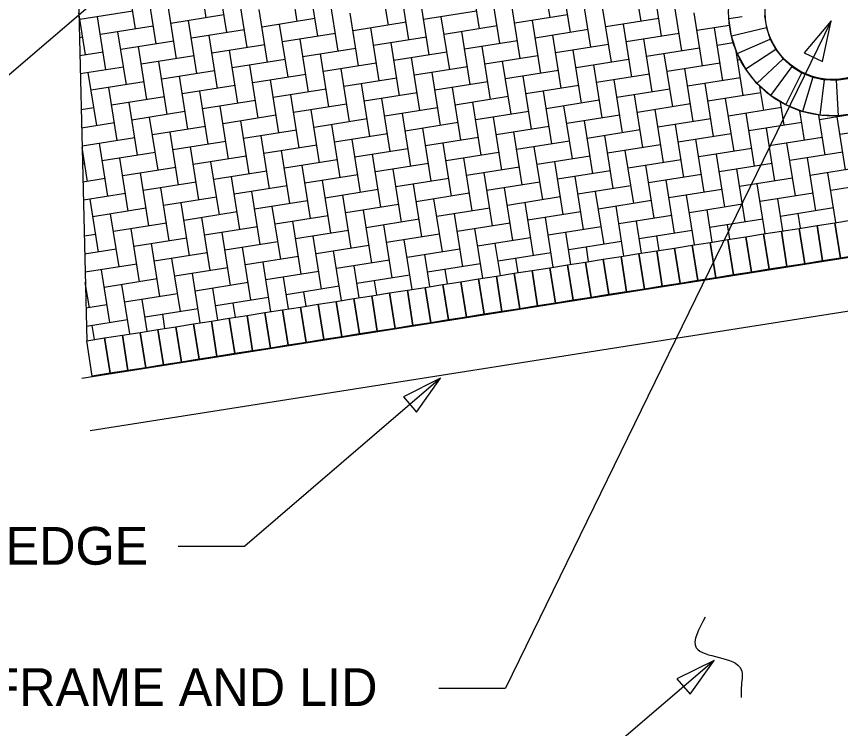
# Model space of a CAD drawing. Extents: x -848 to 1, y -1131 to -115.
# Drawn here: x -814.58 to -783.96, y -835.49 to -809.04 of the extents above; entities that cross this region are included whole.
import ezdxf

# ---------------------------------------------------------------- set-up
doc = ezdxf.new("R2010")
doc.units = 0
for name, color, linetype in [('PM_P_Crosswalk', 7, 'Continuous'), ('PV_P_Joint', 7, 'Continuous'), ('TX_X_5', 7, 'Continuous')]:
    doc.layers.add(name, color=color, linetype=linetype)

msp = doc.modelspace()

# ---------------------------------------------------------------- linework, layer by layer
at = {"layer": 'PM_P_Crosswalk'}
for p, q in [((-766.754, -815.325), (-812.147, -822.484)), ((-766.446, -817.276), (-811.839, -824.435))]:
    msp.add_line(p, q, dxfattribs=at)
at = {"layer": 'PV_P_Joint'}
for p, q in [((-812.301, -807.329), (-811.969, -821.084)), ((-812.301, -807.329), (-811.969, -821.084)), ((-807.528, -809.087), (-807.839, -807.12)), ((-804.145, -809.224), (-804.456, -807.256)), ((-800.762, -809.36), (-801.073, -807.393)), ((-794.755, -809.081), (-795.067, -807.114)), ((-791.372, -809.217), (-791.684, -807.25)), ((-810.151, -809.503), (-810.463, -807.535)), ((-806.768, -809.639), (-807.08, -807.672)), ((-797.379, -809.496), (-797.69, -807.529)), ((-793.996, -809.633), (-794.307, -807.665)), ((-803.385, -809.776), (-803.697, -807.808)), ((-800.002, -809.912), (-800.314, -807.945)), ((-790.613, -809.769), (-790.924, -807.802)), ((-809.391, -810.055), (-809.703, -808.087)), ((-806.008, -810.191), (-806.32, -808.224)), ((-796.619, -810.048), (-796.931, -808.081)), ((-793.236, -810.185), (-793.548, -808.217)), ((-802.625, -810.327), (-802.937, -808.36)), ((-799.242, -810.464), (-799.554, -808.496)), ((-789.853, -810.321), (-790.165, -808.354)), ((-812.015, -810.47), (-812.263, -808.901)), ((-810.255, -808.847), (-812.222, -809.158)), ((-808.632, -810.607), (-808.943, -808.639)), ((-805.249, -810.743), (-805.56, -808.775)), ((-801.866, -810.879), (-802.177, -808.912)), ((-797.483, -808.841), (-799.45, -809.152)), ((-795.859, -810.6), (-796.171, -808.633)), ((-792.476, -810.737), (-792.788, -808.769)), ((-789.093, -810.873), (-789.405, -808.906)), ((-811.255, -811.022), (-811.567, -809.055)), ((-806.872, -808.983), (-808.839, -809.295)), ((-807.872, -811.158), (-808.184, -809.191)), ((-803.489, -809.12), (-805.456, -809.431)), ((-798.483, -811.016), (-798.794, -809.048)), ((-794.1, -808.977), (-796.067, -809.289)), ((-795.1, -811.152), (-795.411, -809.185)), ((-790.717, -809.114), (-792.684, -809.425)), ((-809.495, -809.399), (-811.463, -809.71)), ((-806.112, -809.535), (-808.08, -809.847)), ((-804.489, -811.295), (-804.801, -809.327)), ((-800.106, -809.256), (-802.073, -809.568)), ((-801.106, -811.431), (-801.418, -809.464)), ((-796.723, -809.393), (-798.69, -809.704)), ((-793.34, -809.529), (-795.307, -809.841)), ((-791.717, -811.289), (-792.028, -809.321)), ((-788.086, -809.369), (-789.301, -809.562)), ((-788.334, -811.425), (-788.645, -809.458)), ((-812.118, -809.814), (-812.241, -809.834)), ((-810.495, -811.574), (-810.807, -809.606)), ((-807.112, -811.71), (-807.424, -809.743)), ((-802.729, -809.672), (-804.697, -809.983)), ((-799.346, -809.808), (-801.314, -810.12)), ((-797.723, -811.568), (-798.035, -809.6)), ((-794.34, -811.704), (-794.652, -809.737)), ((-789.957, -809.666), (-791.924, -809.977)), ((-808.735, -809.951), (-810.703, -810.262)), ((-805.352, -810.087), (-807.32, -810.399)), ((-803.729, -811.847), (-804.041, -809.879)), ((-800.346, -811.983), (-800.658, -810.016)), ((-795.963, -809.945), (-797.931, -810.256)), ((-796.963, -812.12), (-797.275, -810.152)), ((-792.58, -810.081), (-794.548, -810.393)), ((-790.957, -811.841), (-791.269, -809.873)), ((-787.946, -810.019), (-788.541, -810.114)), ((-786.576, -809.881), (-786.367, -810.266)), ((-811.359, -810.366), (-812.224, -810.503)), ((-809.736, -812.126), (-810.047, -810.158)), ((-806.353, -812.262), (-806.664, -810.295)), ((-801.97, -810.224), (-803.937, -810.535)), ((-802.97, -812.399), (-803.281, -810.431)), ((-798.587, -810.36), (-800.554, -810.672)), ((-793.58, -812.256), (-793.892, -810.289)), ((-789.197, -810.218), (-791.165, -810.529)), ((-790.197, -812.393), (-790.509, -810.425)), ((-787.574, -811.977), (-787.835, -810.331)), ((-787.802, -810.411), (-787.484, -811.001)), ((-786.367, -810.266), (-787.484, -811.001)), ((-807.976, -810.503), (-809.943, -810.814)), ((-808.976, -812.678), (-809.287, -810.71)), ((-804.593, -810.639), (-806.56, -810.951)), ((-799.587, -812.535), (-799.898, -810.568)), ((-795.204, -810.497), (-797.171, -810.808)), ((-796.204, -812.672), (-796.515, -810.704)), ((-791.821, -810.633), (-793.788, -810.945)), ((-787.688, -810.651), (-787.782, -810.666)), ((-810.599, -810.918), (-812.208, -811.173)), ((-807.216, -811.055), (-809.184, -811.366)), ((-805.593, -812.814), (-805.904, -810.847)), ((-801.21, -810.776), (-803.177, -811.087)), ((-802.21, -812.951), (-802.521, -810.983)), ((-797.827, -810.912), (-799.794, -811.224)), ((-794.444, -811.048), (-796.411, -811.36)), ((-792.821, -812.808), (-793.132, -810.841)), ((-788.438, -810.769), (-790.405, -811.081)), ((-789.438, -812.945), (-789.749, -810.977)), ((-811.599, -813.093), (-811.911, -811.126)), ((-808.216, -813.23), (-808.528, -811.262)), ((-803.833, -811.191), (-805.801, -811.503)), ((-800.45, -811.328), (-802.418, -811.639)), ((-798.827, -813.087), (-799.138, -811.12)), ((-795.444, -813.224), (-795.755, -811.256)), ((-791.061, -811.185), (-793.028, -811.497)), ((-787.678, -811.321), (-789.645, -811.633)), ((-809.839, -811.47), (-811.807, -811.782)), ((-810.839, -813.645), (-811.151, -811.678)), ((-806.456, -811.607), (-808.424, -811.918)), ((-804.833, -813.366), (-805.145, -811.399)), ((-801.45, -813.503), (-801.762, -811.535)), ((-797.067, -811.464), (-799.035, -811.776)), ((-798.067, -813.639), (-798.379, -811.672)), ((-793.684, -811.6), (-795.652, -811.912)), ((-792.061, -813.36), (-792.372, -811.393)), ((-788.678, -813.497), (-788.989, -811.529)), ((-786.814, -812.529), (-786.955, -811.642)), ((-807.456, -813.782), (-807.768, -811.814)), ((-803.073, -811.743), (-805.041, -812.055)), ((-804.073, -813.918), (-804.385, -811.951)), ((-799.69, -811.879), (-801.658, -812.191)), ((-794.684, -813.776), (-794.996, -811.808)), ((-790.301, -811.737), (-792.269, -812.049)), ((-791.301, -813.912), (-791.613, -811.945)), ((-786.918, -811.873), (-788.886, -812.185)), ((-809.08, -812.022), (-811.047, -812.334)), ((-810.08, -814.197), (-810.391, -812.23)), ((-805.697, -812.158), (-807.664, -812.47)), ((-802.314, -812.295), (-804.281, -812.607)), ((-800.69, -814.055), (-801.002, -812.087)), ((-796.307, -812.016), (-798.275, -812.328)), ((-797.307, -814.191), (-797.619, -812.224)), ((-792.924, -812.152), (-794.892, -812.464)), ((-789.541, -812.289), (-791.509, -812.6)), ((-787.918, -814.049), (-788.23, -812.081)), ((-786.055, -813.081), (-786.191, -812.222)), ((-811.703, -812.438), (-812.176, -812.512)), ((-808.32, -812.574), (-810.287, -812.886)), ((-806.697, -814.334), (-807.008, -812.366)), ((-803.314, -814.47), (-803.625, -812.503)), ((-798.931, -812.431), (-800.898, -812.743)), ((-795.548, -812.568), (-797.515, -812.879)), ((-793.924, -814.328), (-794.236, -812.36)), ((-790.541, -814.464), (-790.853, -812.497)), ((-786.158, -812.425), (-788.126, -812.737)), ((-785.295, -813.633), (-785.467, -812.546)), ((-782.775, -812.562), (-784.743, -812.873)), ((-809.32, -814.749), (-809.632, -812.782)), ((-804.937, -812.71), (-806.904, -813.022)), ((-801.554, -812.847), (-803.521, -813.159)), ((-799.931, -814.607), (-800.242, -812.639)), ((-796.548, -814.743), (-796.859, -812.776)), ((-792.165, -812.704), (-794.132, -813.016)), ((-788.782, -812.841), (-790.749, -813.152)), ((-787.158, -814.601), (-787.47, -812.633)), ((-784.535, -814.185), (-784.769, -812.706)), ((-783.775, -814.737), (-784.087, -812.77)), ((-810.943, -812.989), (-812.16, -813.182)), ((-807.56, -813.126), (-809.528, -813.438)), ((-805.937, -814.886), (-806.249, -812.918)), ((-802.554, -815.022), (-802.866, -813.055)), ((-798.171, -812.983), (-800.138, -813.295)), ((-799.171, -815.159), (-799.483, -813.191)), ((-794.788, -813.12), (-796.755, -813.431)), ((-793.165, -814.88), (-793.476, -812.912)), ((-789.782, -815.016), (-790.093, -813.049)), ((-785.399, -812.977), (-787.366, -813.289)), ((-786.399, -815.152), (-786.71, -813.185)), ((-782.016, -813.114), (-783.983, -813.425)), ((-808.56, -815.301), (-808.872, -813.334)), ((-804.177, -813.262), (-806.145, -813.574)), ((-805.177, -815.438), (-805.489, -813.47)), ((-800.794, -813.399), (-802.762, -813.71)), ((-795.788, -815.295), (-796.1, -813.328)), ((-791.405, -813.256), (-793.372, -813.568)), ((-792.405, -815.432), (-792.717, -813.464)), ((-788.022, -813.393), (-789.989, -813.704)), ((-810.184, -813.541), (-812.144, -813.852)), ((-811.184, -815.717), (-811.495, -813.749)), ((-806.801, -813.678), (-808.768, -813.99)), ((-803.418, -813.814), (-805.385, -814.126)), ((-801.794, -815.574), (-802.106, -813.607)), ((-797.411, -813.535), (-799.379, -813.847)), ((-798.411, -815.711), (-798.723, -813.743)), ((-794.028, -813.672), (-795.996, -813.983)), ((-790.645, -813.808), (-792.613, -814.12)), ((-789.022, -815.568), (-789.334, -813.6)), ((-784.639, -813.529), (-786.606, -813.841)), ((-785.639, -815.704), (-785.951, -813.737)), ((-811.943, -815.165), (-812.142, -813.91)), ((-809.424, -814.093), (-811.391, -814.405)), ((-807.801, -815.853), (-808.112, -813.886)), ((-804.418, -815.99), (-804.729, -814.022)), ((-800.035, -813.951), (-802.002, -814.262)), ((-796.652, -814.087), (-798.619, -814.399)), ((-795.028, -815.847), (-795.34, -813.88)), ((-791.645, -815.983), (-791.957, -814.016)), ((-787.262, -813.945), (-789.23, -814.256)), ((-783.879, -814.081), (-785.847, -814.393)), ((-810.424, -816.269), (-810.736, -814.301)), ((-806.041, -814.23), (-808.008, -814.541)), ((-807.041, -816.405), (-807.353, -814.438)), ((-802.658, -814.366), (-804.625, -814.678)), ((-801.035, -816.126), (-801.346, -814.159)), ((-797.652, -816.262), (-797.963, -814.295)), ((-793.269, -814.224), (-795.236, -814.535)), ((-794.269, -816.399), (-794.58, -814.431)), ((-789.886, -814.36), (-791.853, -814.672)), ((-788.262, -816.12), (-788.574, -814.152)), ((-784.879, -816.256), (-785.191, -814.289)), ((-812.047, -814.509), (-812.127, -814.522)), ((-808.664, -814.645), (-810.632, -814.957)), ((-803.658, -816.542), (-803.97, -814.574)), ((-799.275, -814.503), (-801.242, -814.814)), ((-800.275, -816.678), (-800.587, -814.711)), ((-795.892, -814.639), (-797.859, -814.951)), ((-790.886, -816.535), (-791.197, -814.568)), ((-786.503, -814.497), (-788.47, -814.808)), ((-787.503, -816.672), (-787.814, -814.704)), ((-783.12, -814.633), (-785.087, -814.945)), ((-809.664, -816.821), (-809.976, -814.853)), ((-805.281, -814.782), (-807.249, -815.093)), ((-806.281, -816.957), (-806.593, -814.99)), ((-801.898, -814.918), (-803.866, -815.23)), ((-796.892, -816.814), (-797.204, -814.847)), ((-792.509, -814.776), (-794.476, -815.087)), ((-793.509, -816.951), (-793.821, -814.983)), ((-789.126, -814.912), (-791.093, -815.224)), ((-785.743, -815.049), (-787.71, -815.36)), ((-784.138, -816.695), (-784.431, -814.841)), ((-811.288, -815.061), (-812.111, -815.191)), ((-807.905, -815.197), (-809.872, -815.509)), ((-804.522, -815.334), (-806.489, -815.645)), ((-802.898, -817.093), (-803.21, -815.126)), ((-798.515, -815.055), (-800.483, -815.366)), ((-799.515, -817.23), (-799.827, -815.262)), ((-795.132, -815.191), (-797.1, -815.503)), ((-791.749, -815.328), (-793.717, -815.639)), ((-790.126, -817.087), (-790.438, -815.12)), ((-786.761, -817.108), (-787.055, -815.256)), ((-782.36, -815.185), (-784.327, -815.497)), ((-810.528, -815.613), (-812.095, -815.861)), ((-808.905, -817.372), (-809.216, -815.405)), ((-805.522, -817.509), (-805.833, -815.541)), ((-801.139, -815.47), (-803.106, -815.782)), ((-797.756, -815.607), (-799.723, -815.918)), ((-796.132, -817.366), (-796.444, -815.399)), ((-792.749, -817.503), (-793.061, -815.535)), ((-788.366, -815.464), (-790.334, -815.776)), ((-784.983, -815.601), (-786.951, -815.912)), ((-811.528, -817.788), (-811.839, -815.821)), ((-807.145, -815.749), (-809.112, -816.061)), ((-808.145, -817.924), (-808.456, -815.957)), ((-803.762, -815.886), (-805.729, -816.197)), ((-802.139, -817.645), (-802.45, -815.678)), ((-798.756, -817.782), (-799.067, -815.814)), ((-794.373, -815.743), (-796.34, -816.055)), ((-795.373, -817.918), (-795.684, -815.951)), ((-790.99, -815.88), (-792.957, -816.191)), ((-789.385, -817.522), (-789.678, -815.672)), ((-786.105, -817.005), (-786.295, -815.808)), ((-809.768, -816.165), (-811.736, -816.476)), ((-804.762, -818.061), (-805.073, -816.093)), ((-800.379, -816.022), (-802.346, -816.334)), ((-801.379, -818.197), (-801.69, -816.23)), ((-796.996, -816.159), (-798.963, -816.47)), ((-792.008, -817.936), (-792.301, -816.087)), ((-787.607, -816.016), (-789.574, -816.328)), ((-788.729, -817.419), (-788.918, -816.224)), ((-784.224, -816.153), (-786.191, -816.464)), ((-810.768, -818.34), (-811.08, -816.372)), ((-806.385, -816.301), (-808.353, -816.613)), ((-807.385, -818.476), (-807.697, -816.509)), ((-803.002, -816.438), (-804.97, -816.749)), ((-799.619, -816.574), (-801.587, -816.886)), ((-797.996, -818.334), (-798.307, -816.366)), ((-793.613, -816.295), (-795.58, -816.607)), ((-794.632, -818.35), (-794.924, -816.503)), ((-790.23, -816.432), (-792.197, -816.743)), ((-786.847, -816.568), (-788.814, -816.88)), ((-785.449, -816.902), (-785.535, -816.36)), ((-809.008, -816.717), (-810.976, -817.028)), ((-805.625, -816.853), (-807.593, -817.165)), ((-804.002, -818.613), (-804.314, -816.645)), ((-800.619, -818.749), (-800.931, -816.782)), ((-796.236, -816.711), (-798.204, -817.022)), ((-792.853, -816.847), (-794.821, -817.159)), ((-791.352, -817.832), (-791.541, -816.639)), ((-788.073, -817.315), (-788.158, -816.776)), ((-785.496, -816.909), (-784.834, -816.805)), ((-784.834, -816.805), (-784.172, -816.7)), ((-784.172, -816.7), (-783.511, -816.596)), ((-811.632, -817.132), (-812.063, -817.2)), ((-810.008, -818.892), (-810.32, -816.924)), ((-806.625, -819.028), (-806.937, -817.061)), ((-802.242, -816.99), (-804.21, -817.301)), ((-798.859, -817.126), (-800.827, -817.438)), ((-797.256, -818.763), (-797.548, -816.918)), ((-793.976, -818.246), (-794.165, -817.055)), ((-789.47, -816.983), (-791.438, -817.295)), ((-790.697, -817.729), (-790.782, -817.191)), ((-787.481, -817.222), (-786.82, -817.118)), ((-786.82, -817.118), (-786.158, -817.013)), ((-786.158, -817.013), (-785.496, -816.909)), ((-808.249, -817.269), (-810.216, -817.58)), ((-809.249, -819.444), (-809.56, -817.476)), ((-804.866, -817.405), (-806.833, -817.717)), ((-803.242, -819.165), (-803.554, -817.197)), ((-799.879, -819.177), (-800.171, -817.334)), ((-795.476, -817.263), (-797.444, -817.574)), ((-796.6, -818.66), (-796.788, -817.47)), ((-792.093, -817.399), (-794.061, -817.711)), ((-789.467, -817.535), (-788.805, -817.431)), ((-788.805, -817.431), (-788.143, -817.326)), ((-788.143, -817.326), (-787.481, -817.222)), ((-810.872, -817.684), (-812.046, -817.87)), ((-805.866, -819.58), (-806.177, -817.613)), ((-801.483, -817.542), (-803.45, -817.853)), ((-802.503, -819.591), (-802.794, -817.749)), ((-798.1, -817.678), (-800.067, -817.99)), ((-793.32, -818.143), (-793.405, -817.607)), ((-791.452, -817.848), (-790.791, -817.744)), ((-790.791, -817.744), (-790.129, -817.64)), ((-790.129, -817.64), (-789.467, -817.535)), ((-807.489, -817.821), (-809.457, -818.132)), ((-808.489, -819.996), (-808.801, -818.028)), ((-804.106, -817.957), (-806.074, -818.269)), ((-800.723, -818.094), (-802.691, -818.405)), ((-799.223, -819.074), (-799.411, -817.886)), ((-794.717, -817.814), (-796.684, -818.126)), ((-795.944, -818.557), (-796.028, -818.022)), ((-793.438, -818.161), (-792.776, -818.057)), ((-792.776, -818.057), (-792.114, -817.953)), ((-792.114, -817.953), (-791.452, -817.848)), ((-810.112, -818.236), (-812.03, -818.54)), ((-806.729, -818.373), (-808.697, -818.684)), ((-805.126, -820.005), (-805.418, -818.165)), ((-801.847, -819.487), (-802.035, -818.301)), ((-797.34, -818.23), (-799.308, -818.542)), ((-795.423, -818.474), (-794.762, -818.37)), ((-794.762, -818.37), (-794.1, -818.266)), ((-794.1, -818.266), (-793.438, -818.161)), ((-811.112, -820.411), (-811.424, -818.444)), ((-807.75, -820.418), (-808.041, -818.58)), ((-803.346, -818.509), (-805.314, -818.821)), ((-804.47, -819.901), (-804.658, -818.717)), ((-799.963, -818.645), (-801.931, -818.957)), ((-798.567, -818.97), (-798.652, -818.438)), ((-797.409, -818.788), (-796.747, -818.683)), ((-796.747, -818.683), (-796.085, -818.579)), ((-796.085, -818.579), (-795.423, -818.474)), ((-811.872, -819.859), (-812.021, -818.918)), ((-809.353, -818.788), (-811.32, -819.1)), ((-810.373, -820.832), (-810.664, -818.996)), ((-805.97, -818.924), (-807.937, -819.236)), ((-801.191, -819.384), (-801.275, -818.853)), ((-799.394, -819.101), (-798.732, -818.996)), ((-798.732, -818.996), (-798.071, -818.892)), ((-798.071, -818.892), (-797.409, -818.788)), ((-811.976, -819.204), (-812.014, -819.21)), ((-808.593, -819.34), (-810.56, -819.652)), ((-807.094, -820.315), (-807.281, -819.132)), ((-802.587, -819.061), (-804.554, -819.373)), ((-803.814, -819.798), (-803.898, -819.269)), ((-801.38, -819.414), (-800.718, -819.309)), ((-800.718, -819.309), (-800.056, -819.205)), ((-800.056, -819.205), (-799.394, -819.101)), ((-809.718, -820.729), (-809.905, -819.548)), ((-805.21, -819.476), (-807.177, -819.788)), ((-803.365, -819.727), (-802.703, -819.623)), ((-802.703, -819.623), (-802.042, -819.518)), ((-802.042, -819.518), (-801.38, -819.414)), ((-811.216, -819.755), (-811.998, -819.879)), ((-807.833, -819.892), (-809.801, -820.204)), ((-806.438, -820.211), (-806.522, -819.684)), ((-805.351, -820.04), (-804.689, -819.936)), ((-804.689, -819.936), (-804.027, -819.831)), ((-804.027, -819.831), (-803.365, -819.727)), ((-809.062, -820.625), (-809.145, -820.1)), ((-807.336, -820.353), (-806.674, -820.249)), ((-806.674, -820.249), (-806.012, -820.144)), ((-806.012, -820.144), (-805.351, -820.04)), ((-810.457, -820.307), (-811.982, -820.549)), ((-811.685, -821.039), (-811.768, -820.515)), ((-809.322, -820.666), (-808.66, -820.562)), ((-808.66, -820.562), (-807.998, -820.457)), ((-807.998, -820.457), (-807.336, -820.353)), ((-810.645, -820.875), (-809.983, -820.771)), ((-809.983, -820.771), (-809.322, -820.666)), ((-811.969, -821.084), (-811.307, -820.979)), ((-811.307, -820.979), (-810.645, -820.875))]:
    msp.add_line(p, q, dxfattribs=at)
for points in [[(-788.013, -809.775), (-788.109, -809.111), (-787.615, -809.04)], [(-786.781, -809.001), (-786.714, -809.465)], [(-786.714, -809.465), (-788.013, -809.775)], [(-786.713, -809.465), (-786.576, -809.881)], [(-787.802, -810.411), (-788.011, -809.774)], [(-787.802, -810.411), (-786.576, -809.881)], [(-786.367, -810.266), (-786.096, -810.611)], [(-787.069, -811.527), (-786.096, -810.611)], [(-786.095, -810.61), (-785.769, -810.903)], [(-787.069, -811.527), (-787.482, -810.999)], [(-785.769, -810.903), (-786.567, -811.971)], [(-785.768, -810.902), (-785.397, -811.134)], [(-785.998, -812.324), (-785.397, -811.134)], [(-785.396, -811.133), (-784.99, -811.297)], [(-784.99, -811.297), (-785.377, -812.575)], [(-784.989, -811.296), (-784.561, -811.387)], [(-784.123, -811.401), (-783.689, -811.341)], [(-785.998, -812.324), (-786.567, -811.971), (-787.069, -811.527)], [(-784.721, -812.711), (-784.561, -811.387)], [(-784.561, -811.386), (-784.123, -811.402)], [(-784.123, -811.402), (-784.052, -812.733)], [(-785.377, -812.575), (-785.998, -812.324)], [(-782.751, -812.433), (-783.388, -812.64), (-784.052, -812.733), (-784.721, -812.711), (-785.377, -812.575)]]:
    msp.add_lwpolyline(points, dxfattribs=at)
for points in [[(-785.289, -818.223), (-785.496, -816.909), (-784.834, -816.805), (-784.627, -818.118)], [(-784.627, -818.118), (-784.834, -816.805), (-784.172, -816.7), (-783.965, -818.014)], [(-783.965, -818.014), (-784.172, -816.7), (-783.511, -816.596), (-783.303, -817.91)], [(-787.274, -818.536), (-787.481, -817.222), (-786.82, -817.118), (-786.612, -818.431)], [(-786.612, -818.431), (-786.82, -817.118), (-786.158, -817.013), (-785.951, -818.327)], [(-785.951, -818.327), (-786.158, -817.013), (-785.496, -816.909), (-785.289, -818.223)], [(-789.26, -818.849), (-789.467, -817.535), (-788.805, -817.431), (-788.598, -818.745)], [(-788.598, -818.745), (-788.805, -817.431), (-788.143, -817.326), (-787.936, -818.64)], [(-787.936, -818.64), (-788.143, -817.326), (-787.481, -817.222), (-787.274, -818.536)], [(-791.245, -819.162), (-791.452, -817.848), (-790.791, -817.744), (-790.583, -819.058)], [(-790.583, -819.058), (-790.791, -817.744), (-790.129, -817.64), (-789.922, -818.953)], [(-789.922, -818.953), (-790.129, -817.64), (-789.467, -817.535), (-789.26, -818.849)], [(-793.231, -819.475), (-793.438, -818.161), (-792.776, -818.057), (-792.569, -819.371)], [(-792.569, -819.371), (-792.776, -818.057), (-792.114, -817.953), (-791.907, -819.266)], [(-791.907, -819.266), (-792.114, -817.953), (-791.452, -817.848), (-791.245, -819.162)], [(-795.216, -819.788), (-795.423, -818.474), (-794.762, -818.37), (-794.554, -819.684)], [(-794.554, -819.684), (-794.762, -818.37), (-794.1, -818.266), (-793.893, -819.579)], [(-793.893, -819.579), (-794.1, -818.266), (-793.438, -818.161), (-793.231, -819.475)], [(-797.202, -820.101), (-797.409, -818.788), (-796.747, -818.683), (-796.54, -819.997)], [(-796.54, -819.997), (-796.747, -818.683), (-796.085, -818.579), (-795.878, -819.893)], [(-795.878, -819.893), (-796.085, -818.579), (-795.423, -818.474), (-795.216, -819.788)], [(-799.187, -820.414), (-799.394, -819.101), (-798.732, -818.996), (-798.525, -820.31)], [(-798.525, -820.31), (-798.732, -818.996), (-798.071, -818.892), (-797.863, -820.206)], [(-797.863, -820.206), (-798.071, -818.892), (-797.409, -818.788), (-797.202, -820.101)], [(-801.173, -820.728), (-801.38, -819.414), (-800.718, -819.309), (-800.511, -820.623)], [(-800.511, -820.623), (-800.718, -819.309), (-800.056, -819.205), (-799.849, -820.519)], [(-799.849, -820.519), (-800.056, -819.205), (-799.394, -819.101), (-799.187, -820.414)], [(-803.158, -821.041), (-803.365, -819.727), (-802.703, -819.623), (-802.496, -820.936)], [(-802.496, -820.936), (-802.703, -819.623), (-802.042, -819.518), (-801.834, -820.832)], [(-801.834, -820.832), (-802.042, -819.518), (-801.38, -819.414), (-801.173, -820.728)], [(-805.143, -821.354), (-805.351, -820.04), (-804.689, -819.936), (-804.482, -821.249)], [(-804.482, -821.249), (-804.689, -819.936), (-804.027, -819.831), (-803.82, -821.145)], [(-803.82, -821.145), (-804.027, -819.831), (-803.365, -819.727), (-803.158, -821.041)], [(-807.129, -821.667), (-807.336, -820.353), (-806.674, -820.249), (-806.467, -821.562)], [(-806.467, -821.562), (-806.674, -820.249), (-806.012, -820.144), (-805.805, -821.458)], [(-805.805, -821.458), (-806.012, -820.144), (-805.351, -820.04), (-805.143, -821.354)], [(-809.114, -821.98), (-809.322, -820.666), (-808.66, -820.562), (-808.453, -821.876)], [(-808.453, -821.876), (-808.66, -820.562), (-807.998, -820.457), (-807.791, -821.771)], [(-807.791, -821.771), (-807.998, -820.457), (-807.336, -820.353), (-807.129, -821.667)], [(-810.438, -822.189), (-810.645, -820.875), (-809.983, -820.771), (-809.776, -822.084)], [(-809.776, -822.084), (-809.983, -820.771), (-809.322, -820.666), (-809.114, -821.98)], [(-811.762, -822.397), (-811.969, -821.084), (-811.307, -820.979), (-811.1, -822.293)], [(-811.1, -822.293), (-811.307, -820.979), (-810.645, -820.875), (-810.438, -822.189)]]:
    msp.add_lwpolyline(points, close=True, dxfattribs=at)
for radius in [3.86, 2.5]:
    msp.add_circle((-784.258, -808.88), radius, dxfattribs=at)
msp.add_spline([(-788.993, -831.351), (-789.32, -832.484), (-787.652, -833.289), (-787.652, -833.974), (-787.652, -834.332)], degree=3, dxfattribs=at)
at = {"layer": 'TX_X_5'}
for p, q in [((-808.969, -806.158), (-816.244, -812.4)), ((-784.314, -809.204), (-796.414, -833.981)), ((-798.821, -822.473), (-806.097, -828.715)), ((-808.571, -828.715), (-806.097, -828.715)), ((-788.659, -832.953), (-795.935, -839.195)), ((-798.888, -833.981), (-796.414, -833.981))]:
    msp.add_line(p, q, dxfattribs=at)
for points in [[(-784.635, -810.716), (-784.314, -809.204), (-785.309, -810.387)], [(-799.715, -823.734), (-798.821, -822.473), (-800.203, -823.165)], [(-789.553, -834.214), (-788.659, -832.953), (-790.041, -833.645)]]:
    msp.add_lwpolyline(points, close=True, dxfattribs=at)

# ---------------------------------------------------------------- texts
for s, p in [('CONCRETE CROSSWALK EDGE', (-838.496, -829.4)), ('MANHOLE FRAME AND LID', (-825.402, -834.648))]:
    msp.add_text(s, height=1.4, dxfattribs=at).set_placement(p)

doc.saveas('drawing.dxf')
